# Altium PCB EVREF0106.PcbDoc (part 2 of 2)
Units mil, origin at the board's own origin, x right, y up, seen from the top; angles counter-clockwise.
Board outline 3543.31 x 1948.82 mil, 4 copper layers (Top Layer, GND, S2, Bottom Layer); 163 components, 42 nets, 581 pads, 707 vias.
Unrouted connection lines stored in the file: 3.
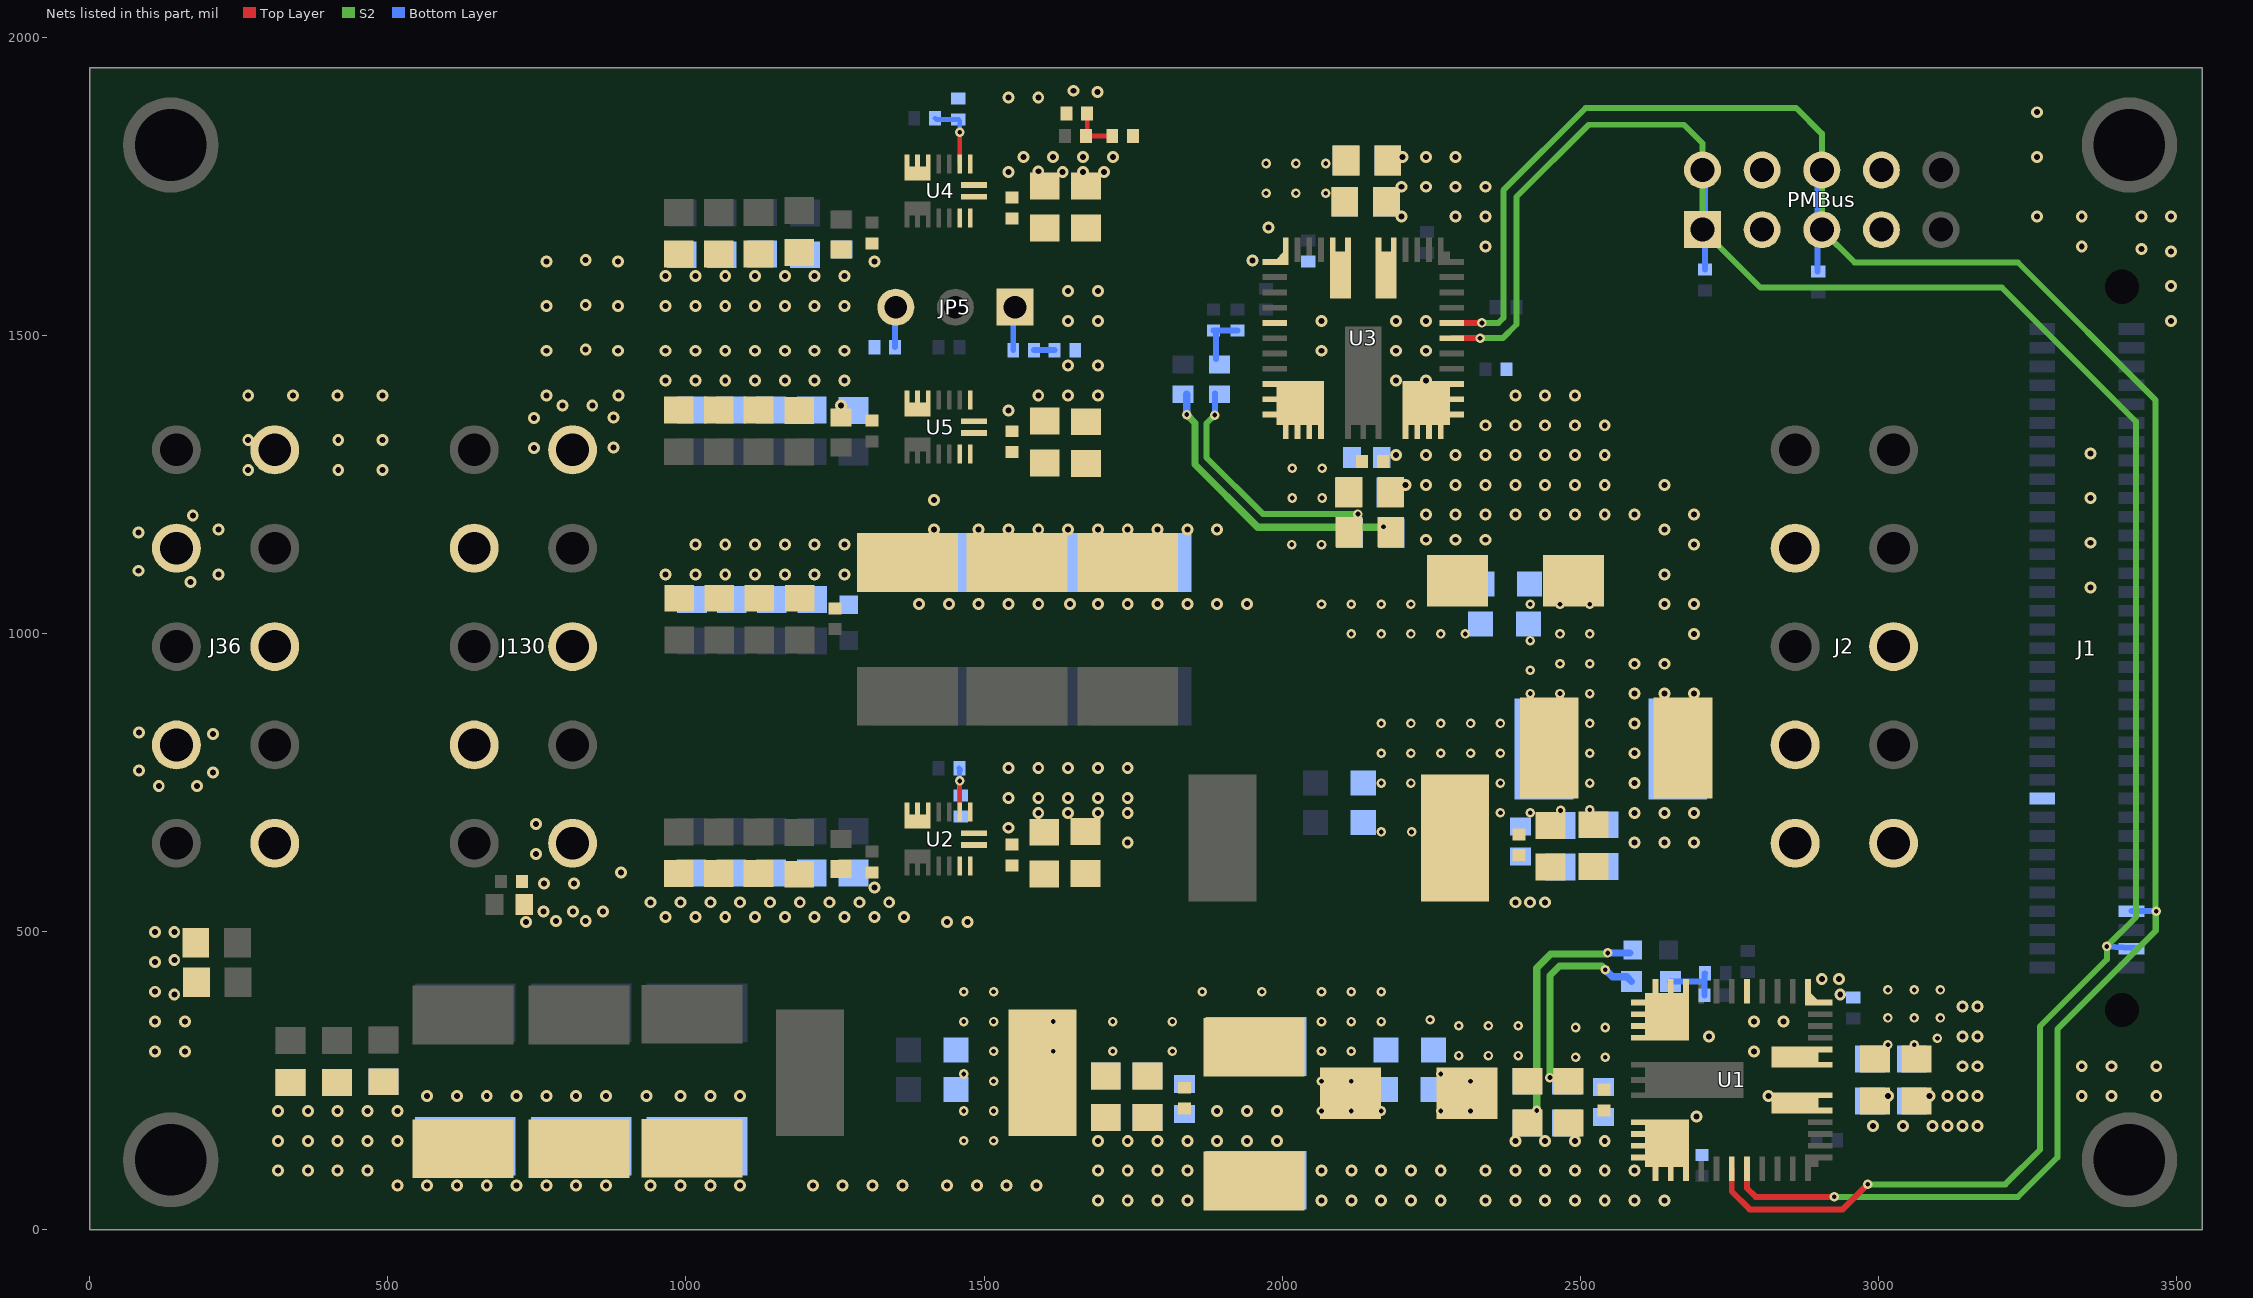
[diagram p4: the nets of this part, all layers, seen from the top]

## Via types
v1: diameter 20, hole 10, Top Layer to Bottom Layer, tented both sides, 417 vias
v2: diameter 16, hole 8, Top Layer to Bottom Layer, tented both sides, 290 vias

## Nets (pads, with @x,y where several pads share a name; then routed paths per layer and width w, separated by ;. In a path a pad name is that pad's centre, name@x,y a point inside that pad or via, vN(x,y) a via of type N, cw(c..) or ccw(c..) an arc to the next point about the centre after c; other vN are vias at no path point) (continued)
GND: C11A.1 C11B.1 C11C.1 C11D.1 C12.1 C12A.1 C12B.1 C13A.1 C13B.1 C13C.1 C13D.1 C14A.1 C14B.1 C14C.1 C15A.1 C15B.1 C15C.1 C21A.1 C21AA.2 C21AB.2 C21AC.1 C21AD.1 C21B.1 C21C.1 C21D.1 C21E.2 C21F.2 C21G.1 C21H.1 C21I.1 C21J.1 C21K.2 C21L.2 C21M.2 C21N.2 C21O.2 C21P.2 C21Q.1 C21R.1 C21S.1 C21T.1 C21U.1 C21V.1 C21W.1 C21X.1 C21Y.2 C21Z.2 C22A.1 C22B.1 C22C.1 C22D.1 C22E.1 C22F.1 C22G.1 C22H.1 C22I.1 C22J.1 C22K.1 C23A.1 C23AC.1 C23AD.1 C23B.1 C23C.1 C23D.1 C23E.2 C23F.2 C23G.1 C23H.1 C23I.1 C23J.1 C23K.2 C23L.2 C23M.2 C23N.2 C23O.2 C23P.2 C23Q.1 C23R.1 C23S.1 C23T.1 C23U.1 C23V.1 C23W.1 C23X.1 C23Y1.2 C23Y.2 C23Z1.2 C23Z.2 C24A.1 C24B.1 C24C.1 C24D.1 C24E.1 C24F.1 C24G.1 C24H.1 C24I.1 C24J.1 C24K.1 C25A.1 C25B.1 C25C.1 C25D.1 C25E.1 C25F.1 C25G.1 C25H.1 C25I.1 C25J.1 C25K.1 C101.1 C103.1 J1.51 J2.2 J2.4 J2.6 J2.8 J36.2 J36.4 J36.6 J36.8 J36.10 J130.2 J130.4 J130.6 J130.8 J130.10 PMBus.3 PMBus.4 PMBus.7 PMBus.8 R22.2 R24.2 R25B.2 R25C.2 R28.2 R41.1 R43.1 R196.1 R396.1 U1.1 U1.5 U1.19 U1.20 U1.21 U1.22 U1.23 U1.24 U1.25 U1.38 U1.39 U1.45 U2.1 U2.16 U3.1 U3.5 U3.19 U3.20 U3.21 U3.22 U3.23 U3.24 U3.25 U3.38 U3.39 U3.45 U4.1 U4.16 U5.1 U5.16 | length 888.5
  S2 w12: v2(1840,1367) 1854,1353 1854,1283 1959,1178 2167,1178 v2@2170,1181 ; v2(2427,200) 2427,439 2450,462 2544,462 v2@2545,463
  Bottom Layer w12: v2(1840,1367) R396.1@1840,1401 ; v2(2546,464) R196.1@2583,464
  other v1: 1691,49 1741,49 1791,49 1841,49 2066,49 2116,49 2166,49 2216,49 2266,49 2341,49 2391,49 2441,49 2491,49 2541,49 2591,49 2641,49 516,74 566,74 616,74 666,74 716,74 766,74 816,74 866,74 941,74 991,74 1041,74 1091,74 1213,74 1263,74 1313,74 1363,74 1438,74 1488,74 1538,74 1588,74 316,99 366,99 416,99 466,99 1691,99 1741,99 1791,99 1841,99 2066,99 2116,99 2166,99 2216,99 2266,99 2341,99 2391,99 2441,99 2491,99 2541,99 2591,99 316,149 366,149 416,149 466,149 516,149 1691,149 1741,149 1791,149 1841,149 1891,149 1941,149 1991,149 2391,149 2441,149 2491,149 2541,149 2991,174 3041,174 3091,174 3116,174 3141,174 3166,174 2695,190 316,199 366,199 416,199 466,199 516,199 1891,199 1941,199 1991,199 566,224 616,224 666,224 716,224 766,224 816,224 866,224 934,224 991,224 1041,224 1091,224 2816,224 3016,224 3086,224 3116,224 3141,224 3166,224 3341,224 3391,224 3466,224 3141,274 3166,274 3341,274 3391,274 3466,274 110,299 160,299 2791,299 2716,324 3141,324 3166,324 110,349 160,349 2791,349 2841,349 3141,374 3166,374 142,394 2936,394 110,399 2905,420 2934,420 110,449 142,452 110,499 142,499 732,516 1438,516 1472,516 782,517.5 832,517.5 966,524 1016,524 1066,524 1116,524 1166,524 1216,524 1266,524 1316,524 1366,524 761,533.5 811,533.5 861,533.5 941,549 991,549 1041,549 1091,549 1141,549 1191,549 1241,549 1291,549 1341,549 2391,549 2416,549 2441,549 1316,574 762,580.5 812,580.5 891,599 748.5,630 1741,649 2591,649 2641,649 2691,649 1541,674 748.5,680 1591,699 1641,699 1691,699 1741,699 2591,699 2641,699 2691,699 1541,724 1591,724 1641,724 1691,724 1741,724 116,744 180,744 2591,749 207,767 83,770 1541,774 1591,774 1641,774 1691,774 1741,774 2591,799 207,831 83,834 2591,849 2591,899 2641,899 2691,899 2591,949 2641,949 2691,999 1391,1049 1441,1049 1491,1049 1541,1049 1591,1049 1644,1049 1691,1049 1741,1049 1791,1049 1841,1049 1891,1049 1941,1049 2641,1049 2691,1049 3356,1077 169,1086 216,1099 966,1099 1016,1099 1066,1099 1116,1099 1166,1099 1216,1099 1266,1099 2641,1099 82,1105 1016,1149 1066,1149 1116,1149 1166,1149 1216,1149 1266,1149 2691,1149 3356,1152 2241,1157 2291,1157 2341,1157 82,1169 216,1174 1416,1174 1491,1174 1541,1174 1591,1174 1641,1174 1691,1174 1741,1174 1791,1174 1841,1174 1891,1174 2641,1174 173,1198 2241,1199 2291,1199 2341,1199 2391,1199 2441,1199 2491,1199 2541,1199 2591,1199 2691,1199 1416,1224 3356,1227 2207,1249 2241,1249 2291,1249 2341,1249 2391,1249 2441,1249 2491,1249 2541,1249 2641,1249 266,1274 417,1274 491,1274 2191,1299 2241,1299 2291,1299 2341,1299 2391,1299 2441,1299 2491,1299 2541,1299 3356,1302 745.5,1311 878.5,1312 266,1324 417,1324 491,1324 2341,1349 2391,1349 2441,1349 2491,1349 2541,1349 745.5,1361 878.5,1362 1541,1374 1260,1382 793,1382.5 843,1382.5 266,1399 341,1399 416,1399 491,1399 766,1399 887,1399 1591,1399 1641,1399 1691,1399 2391,1399 2441,1399 2491,1399 966,1424 1016,1424 1066,1424 1116,1424 1166,1424 1216,1424 1266,1424 2191,1424 2241,1424 1641,1449 1691,1449 766,1474 886,1474 966,1474 1016,1474 1066,1474 1116,1474 1166,1474 1216,1474 1266,1474 2066,1474 2191,1474 2241,1474 832,1476 1641,1524 1691,1524 2066,1524 2191,1524 2241,1524 3491,1524 766,1549 886,1549 966,1549 1016,1549 1066,1549 1116,1549 1166,1549 1216,1549 1266,1549 832,1551 1641,1574 1691,1574 3491,1582.33 966,1599 1016,1599 1066,1599 1116,1599 1166,1599 1216,1599 1266,1599 766,1624 886,1624 1316,1624 1950,1625 832,1626 3491,1640.67 3441,1644.29 2341,1649 3341,1649 1977,1681 2200,1699 2291,1699 2341,1699 3266,1699 3341,1699 3441,1699 3491,1699 2200,1749 2241,1749 2291,1749 2341,1749 1541,1774 1632,1774 1666,1774 1701,1774 1591,1775 1566,1799 1616,1799 1666,1799 1716,1799 2202,1799 2241,1799 2291,1799 3266,1799 3266,1874 1541,1899 1591,1899 1690,1908 1650,1910
  other v2: 2170,1179
NetC31_1: C31.1 R11.2 R199.2 | length 86.4
  Bottom Layer w10: R199.2@2651,416 2700,416 ; C31.1@2708,393 2708,429 R11.2@2709,430
NetC33_1: C33.1 R13.2 R399.2 | length 86
  Bottom Layer w10: C33.1@1885,1508 R13.2@1925,1508 ; R399.2@1889,1460 C33.1@1889,1506
NetJP5_1: JP5.1 R25A.1 | length 70
  Bottom Layer w10: R25A.1@1549,1475 JP5.1@1549,1545
NetJP5_3: JP5.3 R25C.1 | length 67
  Bottom Layer w10: R25C.1@1351,1480 JP5.3@1351,1547
NetR12_2: R12.2 R22.1 U2.2 | length 100.5
  Top Layer w8: U2.2@1459.43,699.28 U2.2@1459.43,700.28 v2(1459.43,752.57)
  Bottom Layer w8: R12.2@1458,774 R12.2@1461,771 ; R22.1@1459,728 R12.2@1459,771
NetR14_2: R14.2 R24.1 U4.2 | length 115.6
  Top Layer w8: U4.2@1459.43,1787.28 v2(1459.43,1840.57)
  Bottom Layer w8: R14.2@1418,1864 1420,1862 R24.1@1457,1862 1459.43,1859.57 v2(1459.43,1840.57)
NetR18_2: R18.2 R28.1 R_EN.2 | length 82.8
  Top Layer w8: R28.1@1673,1872 1673,1836 R_EN.2@1671,1834 R18.2@1715,1834
NetR25A_2: R25A.2 R25B.1 | length 34
  Bottom Layer w10: R25A.2@1584,1475 R25B.1@1618,1475
NetU2_5: U2.5 U2.6 U2.7 U2.15
NetU4_5: U4.5 U4.6 U4.7 U4.15
NetU5_5: U5.5 U5.6 U5.7 U5.15
OUT1: C21A.2 C21B.2 C21C.2 C21D.2 C21Y.1 C21Z.1 L21.1 R110.1 R111.1 R199.1 U1.9 U1.10 U1.11 U1.12 U1.13 U1.14 U1.15 | length 325.4
  S2 w12: v2(2449,255) 2449,426 2465,442 2536,442 v2(2542,436)
  Bottom Layer w12: v2(2542,436) 2554,424 2578,424 R199.1@2586,416
  other v2: 2266,199 2316,199 2316,249 2266,261 2492,289 2542,289 2296,292 2346,292 2396,292 2492,339 2542,339 2296,342 2346,342 2396,342 2248,352
OUT1_1: C21AA.1 C21AB.1 C21E.1 C21F.1 C21G.2 C21H.2 C21I.2 C21J.2 L11.1 L21.2 R110.2 R111.2 R112.1 R113.1
  other v2: 1466,149 1516,149 1466,199 1516,199 2066,199 2116,199 2166,199 1516,249 2066,249 2116,249 1466,261 1516,299 1616,299 1716,299 1816,299 2066,299 2116,299 1466,349 1516,349 1616,349 1716,349 1816,349 2066,349 2116,349 2166,349 1466,399 1516,399 1866,399 1966,399 2066,399 2116,399 2166,399
OUT3: C23A.2 C23B.2 C23C.2 C23D.2 C23Y.1 C23Z.1 L23.1 R114.1 R115.1 R399.1 U3.9 U3.10 U3.11 U3.12 U3.13 U3.14 U3.15 | length 406.1
  S2 w10: v2(1887,1366) 1873,1352 1873,1295 1968,1200 v2(2127,1200)
  Bottom Layer w10: v2(1887,1366) R399.1@1887,1402
  other v2: 2116,999 2166,999 2216,999 2266,999 2307,999 2066,1049 2116,1049 2166,1049 2216,1049 2016,1149 2066,1149 2017,1227 2067,1227 2017,1277 2067,1277
OUT3_1: C23E.1 C23F.1 C23G.2 C23H.2 C23I.2 C23J.2 C23Y1.1 C23Z1.1 L13.1 L23.2 R114.2 R115.2 R116.1 R117.1
  other v2: 2166,667 2217,667 2366,699 2416,699 2467,703 2516,704 2166,749 2216,749 2366,749 2516,749 2166,799 2216,799 2266,799 2316,799 2366,799 2516,799 2166,849 2216,849 2266,849 2316,849 2366,849 2516,849 2416,899 2466,899 2516,899 2416,938 2466,949 2516,949 2416,988 2466,999 2516,999 2416,1049 2466,1049 2516,1049
SCL: J1.68 PMBus.1 PMBus.2 R45.1 U1.28 U3.28 | length 3818.6
  Top Layer w10: U3.28@2284.62,1495 v2(2332,1495) ; U1.28@2754,102.38 2754,64 2784,34 2940,34 v2(2982,76)
  S2 w10: v2(2332,1495) 2370,1495 2393,1518 2393,1732 2514,1853 2674,1853 2705,1822 PMBus.2@2705,1777 PMBus.1@2705,1677 2802,1580 3207,1580 3432,1355 3432,524 v2(3383.05,475.05) 3383.05,453.05 3271,341 3271,134 3213,76 v2(2982,76)
  Bottom Layer w10: R45.1@2709,1610 PMBus.2@2709,1773 ; v2(3383.05,475.05) J1.68@3424.42,472.37 ; J1.68@3424.46,472.37 J1.68@3429.38,472.05
SDA: J1.64 PMBus.5 PMBus.6 R46.1 U1.29 U3.29 | length 3919.3
  Top Layer w10: U3.29@2284.62,1520.59 v2(2335,1520.59) ; U1.29@2779.59,102.38 2779.59,69.41 2794,55 v2(2926,55)
  S2 w10: v2(2335,1520.59) 2362.59,1520.59 2371,1529 2371,1743 2509,1881 2862,1881 2905,1838 PMBus.6@2905,1777 PMBus.5@2905,1677 2960,1622 3234,1622 3465,1391 3465,501 ; v2(2926,55) 3234,55 3300,121 3300,336 3465,501 ; v2(3465.94,534.06) 3465.94,501.94 3465,501
  Bottom Layer w10: R46.1@2898,1607 PMBus.6@2898,1774 ; J1.64@3424.38,534.06 v2(3465.94,534.06)
VIN5V0: C11A.2 C11B.2 C11C.2 C11D.2 C12.2 C12A.2 C12B.2 C13A.2 C13B.2 C13C.2 C13D.2 C14A.2 C14B.2 C14C.2 C15A.2 C15B.2 C15C.2 J2.1 R18.1 U1.40 U1.41 U2.13 U2.14 U3.40 U3.41 U4.13 U4.14 U5.13 U5.14
  other v2: 3016,310 3060,310 3099,321 3016,355 3060,355 3104,355 3016,402 3060,402 3104,402 1973,1738 2023,1738 2073,1738 1973,1788 2023,1788 2073,1788
pads on no net: J1.1 J1.2 J1.3 J1.4 J1.5 J1.6 J1.7 J1.8 J1.9 J1.10 J1.11 J1.12 J1.13 J1.14 J1.15 J1.16 J1.17 J1.18 J1.19 J1.20 J1.21 J1.22 J1.23 J1.24 J1.25 J1.26 J1.27 J1.28 J1.29 J1.30 J1.31 J1.32 J1.33 J1.34 J1.35 J1.36 J1.37 J1.38 J1.39 J1.40 J1.41 J1.42 J1.43 J1.44 J1.45 J1.46 J1.47 J1.48 J1.49 J1.50 J1.52 J1.54 J1.56 J1.58 J1.62 J1.63 J1.65 J1.66 J1.67 J1.70 J1.MH1 J1.MH2 J2.3 J2.5 J2.7 J2.9 J2.10 PMBus.9 PMBus.10 U1.2 U1.7 U1.8 U1.16 U1.17 U1.18 U1.27 U1.33 U1.34 U1.37 U1.42 U1.44 U2.11 U3.2 U3.7 U3.8 U3.16 U3.17 U3.18 U3.27 U3.33 U3.34 U3.37 U3.42 U3.44 U4.11 U5.11

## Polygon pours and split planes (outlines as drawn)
ADC_AVCC on Top Layer "Bottom Layer-No Net 1" (solid, remove dead copper, pour order 47): 1400,144 1400,461 1371,490 410,490 396,500 396,515 409,526 702,526 702,690 682,710 20,710 9,699 9,548 24,533 199,533 218,514 218,332 267,283 1111,283 1127,267 1127,157 1149,135 1391,135
VIN5V0 on Top Layer "Bottom Layer-No Net 1" (solid, remove dead copper, pour order 45): 3119,371 3117,373 3117,418 3213.02,514.02 3213.02,1565.98 3174,1605 2687,1605 2648,1644 2648,1948 2646,1950 2644.82,1948.82 2049,1948.82 2056,1831 2102,1829 2304,1829 2482,1651 2482,1445 2723,1204 2867,1204 2883,1188 2883,773 2857,747 2790,747 2723,680 2723,547 2807,463 2967,463 3065.94,364.05 3110.71,364.05
VIN5V0 on Top Layer "Bottom Layer-No Net 1" (solid, remove dead copper, pour order 71): 1727.6,1226 1729.15,1227.55 1774,1227.55 1832,1227.55 1856,1251.57 1878,1273.58 1878,1476.71 1878,1676.83 1898,1696.85 1917,1715.86 2072,1715.86 2072,1942 2073,1943 2068,1938 1739,1938 1739,1731.87 1724,1716.86 1720.04,1712.89 1712.48,1712.89 1712.48,1630.33 1719,1623.8 1725,1617.8 1725,1521.74 1725,1331.62 1704,1310.6 1698,1304.6 1698,1244.56 1698,1242.56 1705,1235.56 1714.55,1226 1727.6,1226
GND on Top Layer "Bottom Layer-No Net 1" (solid, remove dead copper, pour order 65): 7.41,1933.87 -1.59,1924.87 -1.59,-15.95 3548.41,-15.95 3550.71,-13.64 3550.71,1933.87 7.41,1933.87
VIN5V0 on Top Layer "Bottom Layer-No Net 1" (solid, remove dead copper, pour order 34): 1454,1317 1600.76,1317 1711.8,1317 1730.69,1298.12 1730.69,1261.88 1730.69,1229.54 1727.6,1226.45 1703.13,1226.45 1495.84,1226.45 1482.65,1239.64 1454,1268.29 1454,1317
VIN5V0 on Top Layer "Bottom Layer-No Net 1" (solid, remove dead copper, pour order 33): 1454.67,1713.04 1601.44,1713.04 1712.48,1713.04 1731.36,1694.15 1731.36,1657.92 1731.36,1625.57 1728.27,1622.48 1703.8,1622.48 1496.52,1622.48 1483.33,1635.67 1454.67,1664.33 1454.67,1713.04
DAC_AVCCAUX on Top Layer "Bottom Layer-No Net 1" (solid, remove dead copper, pour order 35): 1411,1724 1334,1724 1329,1729 1327,1731 1327,1774 1327,1947.82 1326,1948.82 1323.82,1951 1269,1951 15,1951 6,1942 3,1939 3,1241 183,1241 192,1250 198,1256 198,1348 198,1430 217,1449 247,1479 450,1479 525,1479 540,1464 549,1455 549,1290 549,1262 561,1250 568,1243 645,1243 671,1243 687,1259 701,1273 701,1458 701,1638 727,1664 737,1674 1412,1674 1412,1722 1410,1724
DAC_AVTT on Top Layer "Bottom Layer-No Net 1" (solid, remove dead copper, pour order 37): 1411,1334 1410,1335 953,1335 845,1227 282,1227 260,1205 260,1088 272,1076 867,1076 1030,1239 1397,1239 1411,1253
VIN5V0 on Top Layer "Bottom Layer-No Net 1" (solid, remove dead copper, pour order 32): 1454,626 1600.76,626 1711.8,626 1730.69,607.12 1730.69,570.88 1730.69,538.54 1727.6,535.45 1703.13,535.45 1495.84,535.45 1482.65,548.64 1454,577.29 1454,626
ADC_AVCCAUX on Top Layer "Bottom Layer-No Net 1" (solid, remove dead copper, pour order 39): 1298,620 1319,620 1336,620 1341,615 1344,612 1344,586 1344,576 1347,573 1349,571 1390,571 1406,571 1409,574 1412,577 1412,613 1412,652 1409,655 1406,658 1369,658 1357,658 1340,675 1329,686 1329,731 1329,790 1318,801 1311,808 1180,808 956,808 918,846 895,869 725,869 278,869 268,859 254,845 254,789 254,746 269,731 276,724 463,724 854,724 916,662 944,634 1041,634 1279,634 1293,620 1298,620
OUT1_1 on Top Layer "Bottom Layer-No Net 1" (solid, remove dead copper, pour order 43): 2205,151 2205,390 2189,406 2172,423 2097,423 1439,423 1430,414 1423,407 1423,377 1423,150 1437,136 1438,137 1540,137 1643,137 1657,151 1660,154 1660,188 1660,214 1669,223 1674,228 1757,228 2039,228 2048,219 2051,216 2051,172 2051,156 2057,150 2061,146 2099,146 2200,146 2204,150
OUT1 on Top Layer "Bottom Layer-No Net 1" (solid, remove dead copper, pour order 44): 2681,431 2679,433 2643,433 2560,433 2512,385 2510,383 2377,383 2236,383 2232,379 2225,372 2225,273 2225,150 2230,145 2285,145 2356,145 2364,153 2365,154 2365,192 2365,219 2369,223 2370,224 2465,224 2552,224 2564,236 2565,237 2565,279 2565,306 2571,312 2576,317 2623,317 2676,317 2680,321 2684,325 2684,357 2684,428 2681,431
DAC_AVCC on Top Layer "Bottom Layer-No Net 1" (solid, remove dead copper, pour order 38): 2073,536 2078,540 2078,912 1975,1018 940,1018 895,1063 16,1063 2,1049 2,907 30,879 904,879 965,818 1731,818 1792,757 1792,551 1807,536
OUT3_1 on Top Layer "Bottom Layer-No Net 1" (solid, remove dead copper, pour order 49): 2355,544 2355,642 2365,652 2549,652 2564,667 2564,1142 2555,1151 2403,1151 2390,1138 2390,925 2376,911 2141,911 2111,879 2111,549 2120,540 2351,540
OUT3 on Top Layer "Bottom Layer-No Net 1" (solid, remove dead copper, pour order 51): 2348,1134 2239,1134 2151,1134 2148,1137 2145,1140 2145,1215 2145,1301 2137,1309 2134,1312 2111,1312 2095,1312 2091,1316 2089,1318 2089,1374 2089,1419 2086,1422 2085,1423 2050,1423 1966,1423 1965,1422 1962,1419 1962,1383 1962,1089 2059,992 2110,941 2287,941 2346,941 2352,947 2358,953 2358,1006 2358,1131 2356,1133 2355,1134 2348,1134
VIN5V0 on Top Layer "Bottom Layer-No Net 1" (solid, remove dead copper, pour order 55): 2132,1566 2132,1851 2129,1854 2124,1859 2083,1859 2030,1859 2024,1853 2015,1844 2015,1776 2015,1747 2067,1695 2080,1682 2080,1562 2129,1562 2130,1563 2132,1565 2132,1566
VIN5V0 on Top Layer "Bottom Layer-No Net 1" (solid, remove dead copper, pour order 57): 1454.97,578.32 1495,538.29 1495,490 1495,455 1502,448 1511,439 1691,439 2187,439 2214,412 2222,404 2356,404 2493,404 2525,436 2539,450 2725,450 2894,450 2907,463 2923,479 2923,572 2923,678 2916,685 2895,706 2822,706 2754,706 2730,682 2723,675 2723,609 2713,599 2689,575 2552,575 2505,575 2468,538 2456,526 2076,526 1793,526 1784,535 1778,541 1778,573 1778,608 1775,611 1758,628 1682,628 1454,628 1454.97,627.03 1454.97,578.32
VIN5V0 on Top Layer "Bottom Layer-No Net 1" (solid, remove dead copper, pour order 54): 2823.71,256.05 3108.71,256.05 3111.71,259.05 3116.71,264.05 3116.71,305.06 3116.71,358.05 3110.71,364.05 3101.71,373.05 3033.71,373.05 3004.71,373.05 2952.71,321.05 2939.71,308.05 2819.71,308.05 2819.71,259.05 2820.71,258.05 2822.71,256.05 2823.71,256.05
VIN5V0 on Top Layer "Bottom Layer-No Net 1" (solid, remove dead copper, pour order 58): 3117,359 3117,539 3104,552 3089,567 3045,567 3002,567 2986,583 2972,597 2972,660 2972,699 2962,709 2954,717 2890,717 2766,717 2745,696 2723,674 2723,607 2723,522 2784,461 2797,448 2894,448 2934,448 2948,434 2969,413 2969,358 2969,337.9 2935.1,304 2935.1,256 3101,256 3110,265 3117,272 3117,359
ADC_AVCC on Bottom Layer "Bottom Layer-No Net 1" (solid, remove dead copper, pour order 41): 265,282 1113,282 1126,269 1126,158 1150,134 1390,134 1400,144 1400,461 1371,490 410,490 396,500 396,515 408,526 700,526 700,692 682,710 20,710 1,691 1,558 25,534 200,534 218,516 218,329
ADC_AVCCAUX on Bottom Layer "Bottom Layer-No Net 1" (solid, remove dead copper, pour order 43): 1322,641 1322,702 1322,795 1318.5,798.5 1308,809 1226,809 966,809 961,804 955,798 955,693 955,641 958,638 962,634 1012,634 1316,634 1322,640
DAC_AVTT on Bottom Layer "Bottom Layer-No Net 1" (solid, remove dead copper, pour order 41): 1323,1334 1259,1334 1099,1334 952,1334 918,1300 894,1276 894,1203 894,1162 902,1154 904,1152 935,1152 944,1152 981,1189 1033,1241 1098,1241 1316,1241 1323,1248 1329,1254 1329,1289 1329,1328 1324,1333
DAC_AVCCAUX on Bottom Layer "Bottom Layer-No Net 1" (solid, remove dead copper, pour order 37): 1323,1674 1324,1675 1324,1800 1324,1942 1321,1945 1320,1944 1056,1944 886,1944 884,1942 878,1936 878,1824 878,1685 887,1676 889,1674 994,1674 1324,1674
GND on Bottom Layer "Bottom Layer-No Net 1" (solid, remove dead copper, pour order 69): -13.33,1949.95 -6.33,1942.95 3522.67,1942.95 3522.67,-3.05 3524.67,-5.05 -16.33,-5.05 -16.33,1948.95 -11.33,1953.95
OUT1_1 on Bottom Layer "Bottom Layer-No Net 1" (solid, remove dead copper, pour order 42): 2204,391 2173,422 1437,422 1423,408 1423,150 1438,135 1638,135 1657,154 1657,216 1670,229 2038,229 2053,214 2053,157 2062,148 2063,149 2201,149 2204,152 2204,158
OUT1 on Bottom Layer "Bottom Layer-No Net 1" (solid, remove dead copper, pour order 45): 2223,373 2223,150 2228,145 2355,145 2365,155 2365,217 2372,224 2556,224 2566,234 2566,369 2552,383 2233,383
DAC_AVCC on Bottom Layer "Bottom Layer-No Net 1" (solid, remove dead copper, pour order 47): 2077,538 2077,764 2077,916 2033,960 1977,1016 1688,1016 941,1016 926,1031 893,1064 802,1064 10,1064 6,1060 0,1054 0,874 11,874 12,875 14,877 72,877 905,877 954,828 965,817 1054,817 1731,817 1778,770 1793,755 1793,627 1793,546 1802,537 1805,534 2056,534 2073,534 2076,537
OUT3_1 on Bottom Layer "Bottom Layer-No Net 1" (solid, remove dead copper, pour order 50): 2390,1134 2391,1133 2391,971 2391,934 2376,919 2373,916 2246,916 2147,916 2124,893 2108,877 2108,676 2108,659 2116,651 2119,648 2410,648 2558,648 2563,653 2568,658 2568,794 2568,1136 2561,1143 2515,1143 2398,1143 2391,1136
OUT3 on Bottom Layer "Bottom Layer-No Net 1" (solid, remove dead copper, pour order 52): 2355,1135 2148,1135 2146,1137 2145,1138 2145,1179 2145,1307 2140,1312 2137,1315 2084,1315 1971,1315 1966,1310 1963,1307 1963,1234 1963,1088 2032,1019 2111,940 2269,940 2346,940 2357,951 2358,952 2358,1131 2354,1135
DAC_VCC on Bottom Layer "Bottom Layer-No Net 1" (solid, remove dead copper, pour order 53): 2353,1462 2354,1461 2354,1438 2354,1430 2352,1428 2351,1427 2340,1427 2313,1427 2310,1430 2307,1433 2307,1444 2307,1459 2308,1460 2310,1462 2353,1462
VIN5V0 on Bottom Layer "Bottom Layer-No Net 1" (solid, remove dead copper, pour order 60): 2953,256 3004,256 3099,256 3109,256 3115,262 3119,266 3119,302 3119,431 3114,436 3112,438 3073,438 2993,438 2988,433 2983,428 2983,374 2983,340 2965,322 2953,310 2953,257
VIN5V0 on Bottom Layer "Bottom Layer-No Net 1" (solid, remove dead copper, pour order 61): 1957,1706 2057,1706 2065,1698 2071,1692 2108,1692 2129,1692 2131,1694 2132,1695 2132,1756 2132,1835 2127,1840 2125,1842 2058,1842 1969,1842 1963,1836 1955,1828 1955,1756 1955,1707
GND on S2 "Bottom Layer-No Net 1" (solid, remove dead copper, pour order 62): -13,1942.16 -6,1935.16 -6,-1.84 3517,-1.84 3519,-3.84 3524,1.16 3524,1942.16 -11,1942.16
GND on GND "Bottom Layer-No Net 1" (solid, remove dead copper, pour order 67): -2.11,1947.02 -0.11,1945.02 -0.11,2.02 3541.89,2.02 3544.89,5.02 3538.89,11.02 3538.89,1953.02 4.89,1953.02 -0.11,1948.02

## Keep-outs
Keep-Out Layer:
  the board outline again, w10

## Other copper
Top Layer:
  rectangle net ADC_AVCC_TAKE: 2886,140 2924,162
  pour cut-out: 702,526 702,492 410,492 400,502 400,515 410,525 701,525
  pour cut-out: 926,1042 926,1125 924,1127 865,1068 899,1068 925,1042
  pour cut-out: 2363.16,544 2378,529.16 2378,529 2346,529 2345,530 2358,543 2361,543
  pour cut-out: 2690.17,311.18 2690.17,286.17 2689,285 2571,285 2571,308 2577,314 2686,314 2689,311
  pour cut-out: 2152.54,1304.12 2166,1317.59 2166,1319 2136,1319 2134,1317 2147,1304 2152,1304
  pour cut-out: 2355,1142.16 2384.84,1142.16 2386,1141 2386,922 2380,916 2142,916 2108,882 2108,547 2124,531 2121,528 2080,528 2080,920 1977,1023 1977,1064 1979,1064 2103,940 2350,940 2362,952 2362,1135.16 2355,1142.16
  pour cut-out: 709.16,1273 749,1233.16 749,1232 663,1232 704,1273
  pour cut-out: 540.84,1262 540,1262 509,1231 511,1229 570,1229 570,1235 543,1262
  pour cut-out: 251.84,1088 231.84,1068 275,1068 256,1087 253,1087
  pour cut-out: 23.88,525.46 23.46,525.46 9,511 9,541 23,527
  pour cut-out: 26.88,871.46 5.41,850 5,850 5,886 10,891 27,874
  pour cut-out: 246.46,848.12 246.46,855.54 228,874 274,874 274,869 253,848
  pour cut-out: 218,715 276,715 249,742 249,746
  pour cut-out: 708.16,692 708.16,692.16 734,718 680,718 705,693
  pour cut-out: 1337,793 1357,813 1318,813 1316,811 1334,793
  pour cut-out: 1440.12,128.46 1439.66,128 1391,128 1406,143 1406,432 1404,434 1473,434 1490,451 1510,431 1510,428 1444,428 1419,403 1419,151 1438,132
  pour cut-out: 2230,136.84 2201,136.84 2200,137.84 2215,152.84 2215,154 2230,139
  pour cut-out: 2576.71,212.49 2557.51,212.49 2555,215 2557,217 2557,226 2563,226 2578,241 2578,214
  pour cut-out: 1459.5,1768.62 1459.5,1713.5 1412.25,1713.5 1412.25,1768.62
  pour cut-out: 1460.5,1373.62 1460.5,1318.5 1413.25,1318.5 1413.25,1373.62
  pour cut-out: 1461.5,682.62 1461.5,627.5 1414.25,627.5 1414.25,682.62
GND:
  pour cut-out: 2531,476 2531,452 2535,448 2558,448 2563,453 2563,477 2558,482 2537,482
S2:
  pour cut-out: 2414,447 2447,480 2529,480 2537,488 2559,488 2566,481 2566,458 2560,452 2467,452 2439,424 2439,192 2434,187 2418,187 2414,191
  pour cut-out: 2182,1168 2182,1186 2177,1191 1959,1191 1864,1286 1864,1363 1846,1381 1830,1381 1826,1377 1826,1356 1843,1339 1843,1274 1952,1165 2179,1165
Bottom Layer:
  pour cut-out: 702,526 702,492 410,492 400,502 400,515 410,525 701,525
  pour cut-out: 2129,640 2085.31,640 2087,641.69 2087,913 1980,1020 1980,1064 2110,934 2343,934 2362,953 2362,1142 2387,1142 2391,1138 2384,1131 2384,931 2371,918 2140,918 2102,880 2102,656.84 2119,639.84
  pour cut-out: 1920.5,1378 1919.5,1377 1814,1377 1814,1464 1809,1469 1813,1473 1824,1473 1824,1541 1853,1570 1883,1570 1920,1533 1920,1381
  pour cut-out: 249.84,1085 235,1070.16 235,1070 267,1070 252,1085
  pour cut-out: 247.46,850.12 247.46,854.54 233,869 268,869 268,865 251,848
  pour cut-out: 246.84,744 217.84,715 279,715 251,743 249,743
  pour cut-out: 1330.16,785 1354,808.84 1354,813 1312,813 1308,809 1329,788 1329,785
  pour cut-out: 1432.23,129.23 1431,128 1391,128 1405,142 1405,465 1406,466 1437,435 1437,424 1436,424 1419,407 1419,142.46
  pour cut-out: 2207,391 2207,372 2214,379 2223,379 2223,380 2234,391
  pour cut-out: 2201,140.84 2224.84,140.84 2226,142 2211,157 2211,152 2202,143
  pour cut-out: 1862,1356 1862,1414 1856,1420 1815,1420 1811,1416 1811,1358 1816,1353 1859,1353
  pour cut-out: 2552,444 2610,444 2616,450 2616,491 2612,495 2554,495 2537,494 2534,491 2533,450 2549,447
Multi-Layer:
  pour cut-out: 1822,1355 1855,1355 1860,1360 1860,1376 1855,1381 1825,1381 1822,1378

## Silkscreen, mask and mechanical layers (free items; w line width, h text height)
Top Overlay:
  region: 198.3,1621.51 198.3,1676.51 178.3,1676.51 178.3,1621.51 148.3,1621.51 148.3,1676.51 128.3,1676.51 128.3,1621.51 103.3,1621.51 103.3,1696.51 118.3,1711.51 208.3,1711.51 223.3,1696.51 223.3,1621.51
  region: 243.3,1672.51 243.3,1696.51 257.3,1711.51 338.3,1711.51 353.3,1696.51 353.3,1672.51 332.3,1672.51 332.3,1691.51 267.3,1691.51 267.3,1672.51
  region: 243.3,1621.51 243.3,1676.51 353.3,1676.51 353.3,1671.51 338.3,1656.51 268.3,1656.51 268.3,1621.51
  region: 288.3,1641.51 438.3,1641.51 438.3,1656.51 388.3,1656.51 373.3,1671.51 373.3,1696.51 388.3,1711.51 463.3,1711.51 469.3,1706.51 469.3,1696.51 464.3,1691.51 398.3,1691.51 398.3,1676.51 453.3,1676.51 468.3,1661.51 468.3,1636.51 453.3,1621.51 288.3,1621.51
  lines w4: 103.3,1621.51 103.3,1696.51 118.3,1711.51 208.3,1711.51 223.3,1696.51 223.3,1621.51 198.3,1621.51 198.3,1676.51 178.3,1676.51 178.3,1621.51 148.3,1621.51 148.3,1676.51 128.3,1676.51 128.3,1621.51 103.3,1621.51 ; 243.3,1621.51 268.3,1621.51 268.3,1656.51 338.3,1656.51 353.3,1671.51 353.3,1696.51 338.3,1711.51 258.3,1711.51 243.3,1696.51 243.3,1621.51 ; 268.3,1676.51 333.3,1676.51 333.3,1691.51 268.3,1691.51 268.3,1676.51 ; 288.3,1621.51 288.3,1641.51 438.3,1641.51 438.3,1656.51 388.3,1656.51 373.3,1671.51 373.3,1676.51 373.3,1696.51 388.3,1711.51 464.3,1711.51 469.3,1706.51 469.3,1696.51 464.3,1691.51 398.3,1691.51 398.3,1676.51 453.3,1676.51 468.3,1661.51 468.3,1646.51 468.3,1636.51 453.3,1621.51 288.3,1621.51
  lines w5: 0,0 406.69,0
  text "2.8V" at 1515,1607 h30
  text "3V" at 1335,1605 h30
  text "Monolithic Power Systems" at 105,1559 h40
  text "EVREF0106" at 109,1490 h40
  text "SCL" at 2709,1449 h30 r90
  text "GND" at 2813.67,1449 h30 r90
  text "SDA" at 2918.33,1449 h30 r90
  text "GND" at 3023,1449 h30 r90
  text "www.monolithicpower.com" at 105,1438 h40
Mechanical 6:
  lines w2: 0,0 0,1948.82

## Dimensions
3379.28,19.96 to 2972.59,19.96 on Mechanical 1
2944.61,1044.99 to 729.26,1060.99 on Mechanical 1
245.27,2027 to 744.79,2027 on Mechanical 1
310.43,647.99 to 645,647.99 on Mechanical 1
227.55,910 to 0,0 on Mechanical 1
